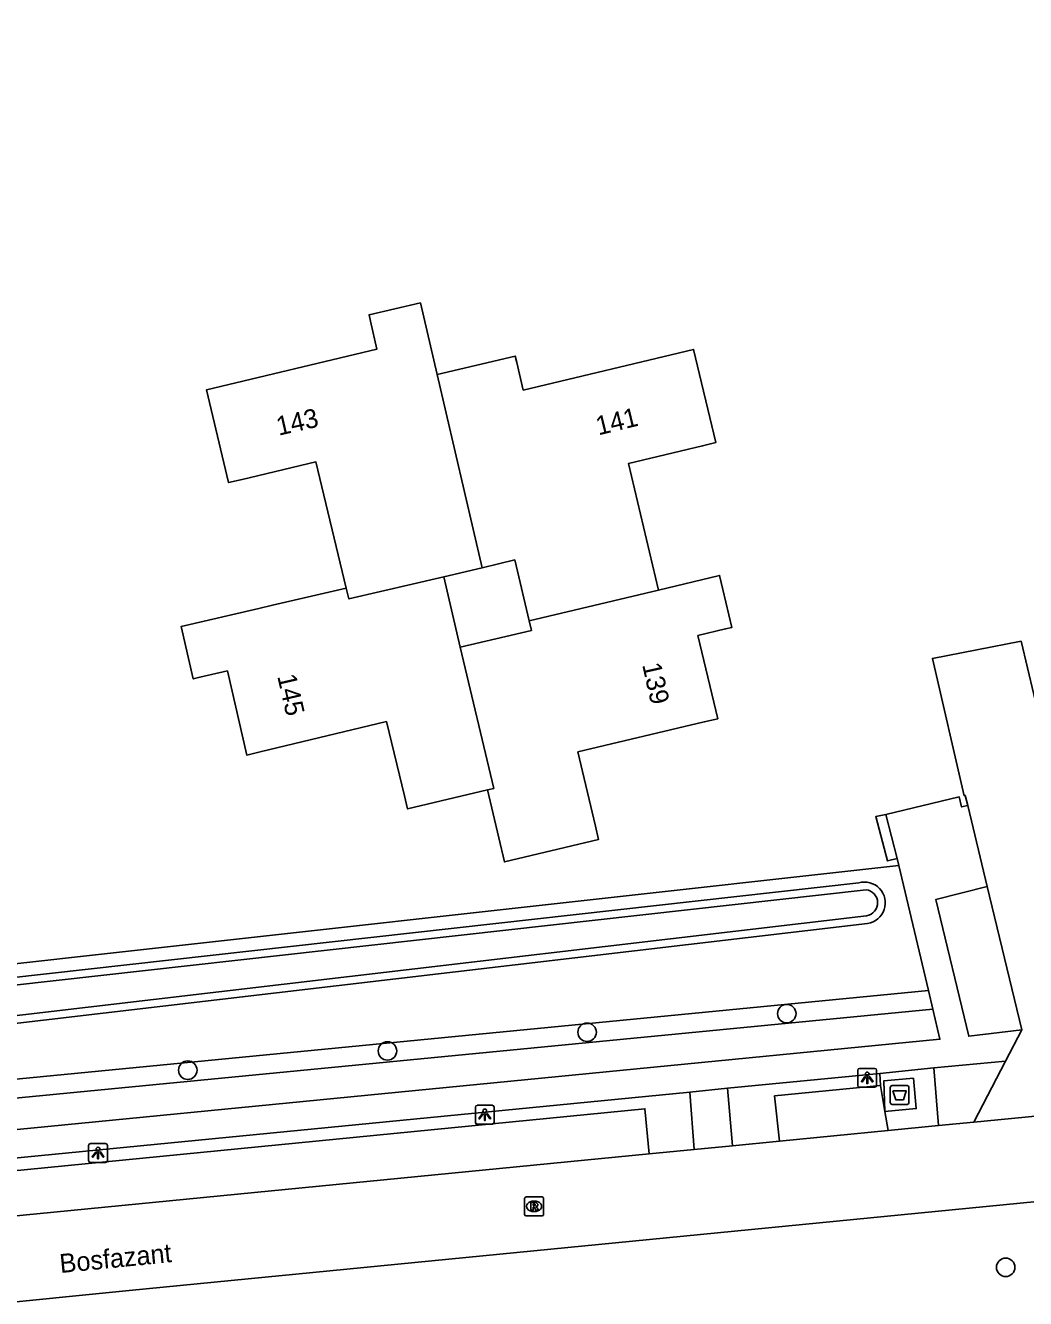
# Model space of a CAD drawing. Extents: x 156664 to 157568, y 383571 to 384421.
# Drawn here: x 156906.9 to 156959.8, y 383915 to 383982.4 of the extents above; entities that cross this region are included whole.
import ezdxf

# ---------------------------------------------------------------- set-up
doc = ezdxf.new("R2010")
doc.units = 0
for name, color, linetype in [('IMGEO_Afval_apart_plaats', 7, 'Continuous'), ('IMGEO_Boom', 7, 'Continuous'), ('IMGEO_Groenvoorziening', 7, 'Continuous'), ('IMGEO_Haag', 7, 'Continuous'), ('IMGEO_Hek', 7, 'Continuous'), ('IMGEO_Lichtpunt', 7, 'Continuous'), ('IMGEO_Muur', 7, 'Continuous'), ('IMGEO_Openbare_ruimte_label', 7, 'Continuous'), ('IMGEO_Pand', 7, 'Continuous'), ('IMGEO_Pand_nummerreeks', 7, 'Continuous'), ('IMGEO_Parkeervlak_open', 7, 'Continuous'), ('IMGEO_Rijbaan_lokaal_open', 7, 'Continuous'), ('IMGEO_Rioolput', 7, 'Continuous'), ('IMGEO_Voetpad_gesloten', 7, 'Continuous'), ('IMGEO_Voetpad_op_trap', 7, 'Continuous'), ('IMGEO_Voetpad_open', 7, 'Continuous'), ('IMGEO_Waterloop', 7, 'Continuous')]:
    doc.layers.add(name, color=color, linetype=linetype)

msp = doc.modelspace()

# ---------------------------------------------------------------- linework, layer by layer
at = {"layer": 'IMGEO_Afval_apart_plaats'}
for p, q in [((156952.644, 383925.35), (156952.644, 383926.15)), ((156952.644, 383926.15), (156952.644, 383925.35)), ((156952.744, 383926.25), (156953.534, 383926.25)), ((156953.534, 383926.25), (156952.744, 383926.25)), ((156953.634, 383926.15), (156953.634, 383925.35)), ((156953.634, 383925.35), (156953.634, 383926.15)), ((156953.534, 383925.25), (156952.744, 383925.25)), ((156952.744, 383925.25), (156953.534, 383925.25))]:
    msp.add_line(p, q, dxfattribs=at)
msp.add_lwpolyline([(156952.787, 383925.964), (156953.491, 383925.964), (156953.342, 383925.494), (156952.936, 383925.494), (156952.787, 383925.964)], dxfattribs=at)
for centre, start, end in [((156952.744, 383926.15), 90, 180), ((156952.744, 383926.15), 90, 180), ((156953.534, 383926.15), 0, 90), ((156953.534, 383926.15), 360, 90), ((156952.744, 383925.35), 180, 270), ((156952.744, 383925.35), 180, 270), ((156953.534, 383925.35), 270, 0), ((156953.534, 383925.35), 270, 0)]:
    msp.add_arc(centre, 0.1, start, end, dxfattribs=at)
at = {"layer": 'IMGEO_Boom'}
for centre in [(156947.168, 383930.057), (156936.598, 383929.071), (156926.029, 383928.083), (156915.457, 383927.063), (156958.758, 383916.622)]:
    msp.add_circle(centre, 0.489, dxfattribs=at)
at = {"layer": 'IMGEO_Groenvoorziening'}
for points in [[(156953.099, 383937.896), (156882.007, 383929.988), (156863.465, 384006.689), (156971.911, 384032.865), (156984.848, 383993.384), (157001.305, 383943.16), (156963.71, 383939.037)], [(156882.291, 383929.295), (156950.98, 383936.984)], [(156951.446, 383934.836), (156882.827, 383926.782)]]:
    msp.add_lwpolyline(points, dxfattribs=at)
msp.add_arc((156951.283, 383935.925), 1.101, 278.50054, 105.98028, dxfattribs=at)
at = {"layer": 'IMGEO_Haag'}
for points in [[(156954.665, 383931.279), (156875.116, 383923.557), (156857.538, 383999.895), (156855.447, 384008.779)], [(156874.835, 383922.525), (156954.897, 383930.297)]]:
    msp.add_lwpolyline(points, dxfattribs=at)
at = {"layer": 'IMGEO_Hek'}
msp.add_lwpolyline([(156953.099, 383937.896), (156882.007, 383929.988), (156863.465, 384006.689), (156971.911, 384032.865), (156984.848, 383993.384), (157001.305, 383943.16)], dxfattribs=at)
at = {"layer": 'IMGEO_Lichtpunt'}
for p, q in [((156950.928, 383927.06), (156950.928, 383926.253)), ((156950.928, 383927.06), (156950.928, 383926.253)), ((156951.83, 383927.155), (156951.022, 383927.155)), ((156951.83, 383927.155), (156951.022, 383927.155)), ((156951.924, 383926.253), (156951.924, 383927.06)), ((156951.924, 383926.253), (156951.924, 383927.06)), ((156951.022, 383926.159), (156951.83, 383926.159)), ((156951.022, 383926.159), (156951.83, 383926.159)), ((156930.681, 383925.106), (156930.681, 383924.299)), ((156930.681, 383925.106), (156930.681, 383924.299)), ((156931.583, 383925.201), (156930.775, 383925.201)), ((156931.583, 383925.201), (156930.775, 383925.201)), ((156931.677, 383924.299), (156931.677, 383925.106)), ((156931.677, 383924.299), (156931.677, 383925.106)), ((156930.775, 383924.205), (156931.583, 383924.205)), ((156930.775, 383924.205), (156931.583, 383924.205)), ((156910.207, 383923.08), (156910.207, 383922.273)), ((156910.207, 383923.08), (156910.207, 383922.273)), ((156911.109, 383923.175), (156910.301, 383923.175)), ((156911.109, 383923.175), (156910.301, 383923.175)), ((156911.203, 383922.273), (156911.203, 383923.08)), ((156911.203, 383922.273), (156911.203, 383923.08)), ((156910.301, 383922.179), (156911.109, 383922.179)), ((156910.301, 383922.179), (156911.109, 383922.179))]:
    msp.add_line(p, q, dxfattribs=at)
for points in [[(156951.302, 383926.724), (156951.341, 383926.696), (156951.153, 383926.434), (156951.115, 383926.461), (156951.302, 383926.724)], [(156951.404, 383926.676), (156951.451, 383926.676), (156951.451, 383926.354), (156951.404, 383926.354), (156951.404, 383926.676)], [(156951.514, 383926.696), (156951.552, 383926.723), (156951.739, 383926.461), (156951.7, 383926.433), (156951.514, 383926.696)], [(156931.055, 383924.77), (156931.094, 383924.742), (156930.906, 383924.48), (156930.868, 383924.507), (156931.055, 383924.77)], [(156931.157, 383924.722), (156931.204, 383924.722), (156931.204, 383924.4), (156931.157, 383924.4), (156931.157, 383924.722)], [(156931.267, 383924.742), (156931.305, 383924.769), (156931.492, 383924.507), (156931.453, 383924.479), (156931.267, 383924.742)], [(156910.581, 383922.744), (156910.62, 383922.716), (156910.432, 383922.454), (156910.394, 383922.481), (156910.581, 383922.744)], [(156910.683, 383922.696), (156910.73, 383922.696), (156910.73, 383922.374), (156910.683, 383922.374), (156910.683, 383922.696)], [(156910.793, 383922.716), (156910.831, 383922.743), (156911.018, 383922.481), (156910.979, 383922.453), (156910.793, 383922.716)]]:
    msp.add_lwpolyline(points, dxfattribs=at)
for centre in [(156951.427, 383926.858), (156931.18, 383924.904), (156910.706, 383922.878)]:
    msp.add_circle(centre, 0.0994, dxfattribs=at)
for centre, start, end in [((156951.022, 383927.06), 90, 180), ((156951.022, 383927.06), 90, 180), ((156951.83, 383927.06), 0, 90), ((156951.83, 383927.06), 0, 90), ((156951.022, 383926.253), 180, 270), ((156951.022, 383926.253), 180, 270), ((156951.83, 383926.253), 270, 0), ((156951.83, 383926.253), 270, 360), ((156930.775, 383925.106), 90, 180), ((156930.775, 383925.106), 90, 180), ((156931.583, 383925.106), 0, 90), ((156931.583, 383925.106), 0, 90), ((156930.775, 383924.299), 180, 270), ((156930.775, 383924.299), 180, 270), ((156931.583, 383924.299), 270, 0), ((156931.583, 383924.299), 270, 360), ((156910.301, 383923.08), 90, 180), ((156910.301, 383923.08), 90, 180), ((156911.109, 383923.08), 0, 90), ((156911.109, 383923.08), 0, 90), ((156910.301, 383922.273), 180, 270), ((156910.301, 383922.273), 180, 270), ((156911.109, 383922.273), 270, 0), ((156911.109, 383922.273), 270, 360)]:
    msp.add_arc(centre, 0.0946, start, end, dxfattribs=at)
at = {"layer": 'IMGEO_Muur'}
for points in [[(156956.745, 383941.083), (156956.425, 383941.002)], [(156953.011, 383938.269), (156952.494, 383938.147), (156951.881, 383940.49), (156952.407, 383940.603)], [(156952.407, 383940.603), (156953.011, 383938.269)]]:
    msp.add_lwpolyline(points, dxfattribs=at)
at = {"layer": 'IMGEO_Pand'}
for points in [[(156923.85, 383952.595), (156922.236, 383959.272), (156918.344, 383958.349), (156917.614, 383958.176), (156916.439, 383963.089), (156925.467, 383965.244), (156925.136, 383966.72), (156925.059, 383967.061), (156927.769, 383967.693), (156928.654, 383963.895)], [(156940.369, 383952.489), (156938.787, 383959.187), (156942.711, 383960.123), (156943.41, 383960.293), (156942.232, 383965.227), (156933.219, 383963.073), (156932.871, 383964.538), (156932.791, 383964.879), (156928.654, 383963.895)], [(156928.654, 383963.895), (156931.036, 383953.671)], [(156931.036, 383953.671), (156932.77, 383954.08), (156933.53, 383950.858)], [(156929.004, 383953.191), (156923.989, 383952.018), (156923.85, 383952.595)], [(156931.036, 383953.671), (156929.004, 383953.191)], [(156929.884, 383949.462), (156929.004, 383953.191)], [(156940.369, 383952.489), (156943.612, 383953.263), (156943.79, 383952.515), (156944.266, 383950.508), (156943.925, 383950.427), (156942.462, 383950.08), (156943.511, 383945.674), (156942.799, 383945.503), (156936.11, 383943.912), (156937.042, 383939.99), (156937.205, 383939.281), (156932.219, 383938.091), (156931.317, 383941.9)], [(156923.85, 383952.595), (156919.943, 383951.681), (156919.213, 383951.51), (156915.1, 383950.548), (156915.747, 383947.783), (156916.098, 383947.865), (156917.553, 383948.206), (156918.575, 383943.752), (156919.289, 383943.923), (156925.972, 383945.518), (156926.929, 383941.592), (156927.095, 383940.901), (156931.317, 383941.9)], [(156933.53, 383950.858), (156940.369, 383952.489)], [(156929.884, 383949.462), (156933.65, 383950.35), (156933.53, 383950.858)], [(156931.317, 383941.9), (156931.657, 383941.98), (156929.884, 383949.462)]]:
    msp.add_lwpolyline(points, dxfattribs=at)
at = {"layer": 'IMGEO_Parkeervlak_open'}
for points in [[(156952.134, 383926.243), (156946.522, 383925.696), (156946.775, 383923.3)], [(156853.805, 383916.581), (156939.653, 383925.02), (156939.883, 383922.625)]]:
    msp.add_lwpolyline(points, dxfattribs=at)
at = {"layer": 'IMGEO_Rijbaan_lokaal_open'}
for points in [[(156962.748, 383943.053), (156961.579, 383942.807), (156961.704, 383942.271), (156961.383, 383942.196), (156961.258, 383942.72), (156959.573, 383949.776), (156954.882, 383948.869), (156956.564, 383941.597), (156956.615, 383941.611), (156956.745, 383941.083)], [(156957.783, 383936.781), (156956.745, 383941.083)], [(156957.783, 383936.781), (156959.604, 383929.198)], [(156958.753, 383927.533), (156959.604, 383929.198)], [(156958.753, 383927.533), (156957.067, 383924.307)], [(156970.285, 383925.601), (156957.067, 383924.307)], [(156955.199, 383924.125), (156952.527, 383923.863)], [(156957.067, 383924.307), (156955.199, 383924.125)], [(156952.527, 383923.863), (156946.775, 383923.3)], [(156942.261, 383922.858), (156939.883, 383922.625)], [(156944.299, 383923.058), (156942.261, 383922.858)], [(156946.775, 383923.3), (156944.299, 383923.058)], [(156939.883, 383922.625), (156858.629, 383914.671)], [(156867.996, 383911.037), (156904.417, 383914.609), (156912.352, 383915.387), (156960.429, 383920.102)]]:
    msp.add_lwpolyline(points, dxfattribs=at)
at = {"layer": 'IMGEO_Rioolput'}
for p, q in [((156933.289, 383919.425), (156933.289, 383920.277)), ((156933.364, 383920.351), (156934.216, 383920.351)), ((156933.777, 383920.131), (156933.802, 383920.131)), ((156934.29, 383920.277), (156934.29, 383919.425)), ((156933.8, 383919.571), (156933.775, 383919.571)), ((156934.216, 383919.351), (156933.364, 383919.351))]:
    msp.add_line(p, q, dxfattribs=at)
for points in [[(156933.289, 383919.425), (156933.289, 383920.277)], [(156933.364, 383920.351), (156934.216, 383920.351)], [(156934.29, 383920.277), (156934.29, 383919.425)], [(156933.878, 383920.049), (156933.626, 383920.051), (156933.626, 383919.651)], [(156933.626, 383919.651), (156933.75, 383919.651), (156933.75, 383919.813), (156933.761, 383919.813)], [(156933.804, 383919.97), (156933.75, 383919.97), (156933.75, 383919.889)], [(156933.75, 383919.889), (156933.802, 383919.889)], [(156933.808, 383919.784), (156933.879, 383919.651), (156934.019, 383919.651), (156933.954, 383919.777)], [(156934.216, 383919.351), (156933.364, 383919.351)]]:
    msp.add_lwpolyline(points, dxfattribs=at)
for centre, radius, start, end in [((156933.366, 383920.275), 0.0765, 91.55205, 178.44795), ((156933.366, 383920.275), 0.0765, 91.55205, 178.44795), ((156934.214, 383920.275), 0.0765, 1.55205, 88.44795), ((156934.214, 383920.275), 0.0765, 1.55205, 88.44795), ((156933.366, 383919.427), 0.0765, 181.55205, 268.44795), ((156933.366, 383919.427), 0.0765, 181.55205, 268.44795), ((156933.76, 383919.76), 0.0533, 26.02933, 88.69889), ((156933.786, 383920.078), 0.19, 274.7715, 282.96867), ((156933.81, 383919.874), 0.0964, 77.00612, 93.18647), ((156933.824, 383919.931), 0.0378, 276.66336, 79.67722), ((156933.877, 383919.939), 0.109, 350.36119, 89.41601), ((156933.875, 383919.939), 0.112, 277.58423, 350.98172), ((156933.859, 383919.724), 0.108, 29.51342, 73.79051), ((156934.214, 383919.427), 0.0765, 271.55205, 358.44795), ((156934.214, 383919.427), 0.0765, 271.55205, 358.44795)]:
    msp.add_arc(centre, radius, start, end, dxfattribs=at)
for centre, major_axis, ratio, start_param, end_param in [((156933.776, 383919.851), (-0.387, 0.002), 0.722429, 4.712389, 7.853982), ((156933.801, 383919.851), (-0.39, 0.002), 0.717154, 1.570796, 4.712389)]:
    msp.add_ellipse(centre, major_axis=major_axis, ratio=ratio, start_param=start_param, end_param=end_param, dxfattribs=at)
at = {"layer": 'IMGEO_Voetpad_gesloten'}
msp.add_lwpolyline([(156952.36, 383924.875), (156952.302, 383926.49), (156953.871, 383926.637), (156954.021, 383925.029), (156952.36, 383924.875)], dxfattribs=at)
at = {"layer": 'IMGEO_Voetpad_op_trap'}
for points in [[(156942.029, 383925.893), (156942.261, 383922.858)], [(156944.299, 383923.058), (156944.032, 383926.112)]]:
    msp.add_lwpolyline(points, dxfattribs=at)
at = {"layer": 'IMGEO_Voetpad_open'}
for points in [[(156956.745, 383941.083), (156956.425, 383941.002), (156956.295, 383941.53), (156952.407, 383940.603)], [(156953.011, 383938.269), (156953.099, 383937.896)], [(156953.099, 383937.896), (156954.665, 383931.279)], [(156959.604, 383929.198), (156956.799, 383928.862), (156955.061, 383936.102), (156957.783, 383936.781)], [(156954.665, 383931.279), (156954.897, 383930.297)], [(156954.897, 383930.297), (156955.275, 383928.7), (156875.218, 383920.862)], [(156954.952, 383927.178), (156958.753, 383927.533)], [(156944.032, 383926.112), (156952.092, 383926.89)], [(156954.952, 383927.178), (156952.092, 383926.89)], [(156952.092, 383926.89), (156952.134, 383926.243)], [(156955.199, 383924.125), (156954.952, 383927.178)], [(156952.134, 383926.243), (156952.36, 383924.875)], [(156853.282, 383917.324), (156868.496, 383918.711), (156942.029, 383925.893)], [(156942.029, 383925.893), (156944.032, 383926.112)], [(156952.36, 383924.875), (156952.527, 383923.863)]]:
    msp.add_lwpolyline(points, dxfattribs=at)
at = {"layer": 'IMGEO_Waterloop'}
for points in [[(156951.362, 383936.616), (156882.303, 383928.888)], [(156882.795, 383927.187), (156951.392, 383935.238)]]:
    msp.add_lwpolyline(points, dxfattribs=at)
msp.add_arc((156951.284, 383935.925), 0.695, 278.96102, 83.53332, dxfattribs=at)

# ---------------------------------------------------------------- texts
at = {"layer": 'IMGEO_Openbare_ruimte_label'}
msp.add_text('Bosfazant', height=1, rotation=5.62506, dxfattribs=at).set_placement((156908.716, 383916.319))
at = {"layer": 'IMGEO_Pand_nummerreeks'}
for s, rotation, p in [('143', 12.83757, (156920.271, 383960.659)), ('141', 13.67621, (156937.197, 383960.674)), ('139', 282.76097, (156939.508, 383948.532)), ('145', 282.95674, (156920.189, 383947.925))]:
    msp.add_text(s, height=1, rotation=rotation, dxfattribs=at).set_placement(p)

doc.saveas('drawing.dxf')
